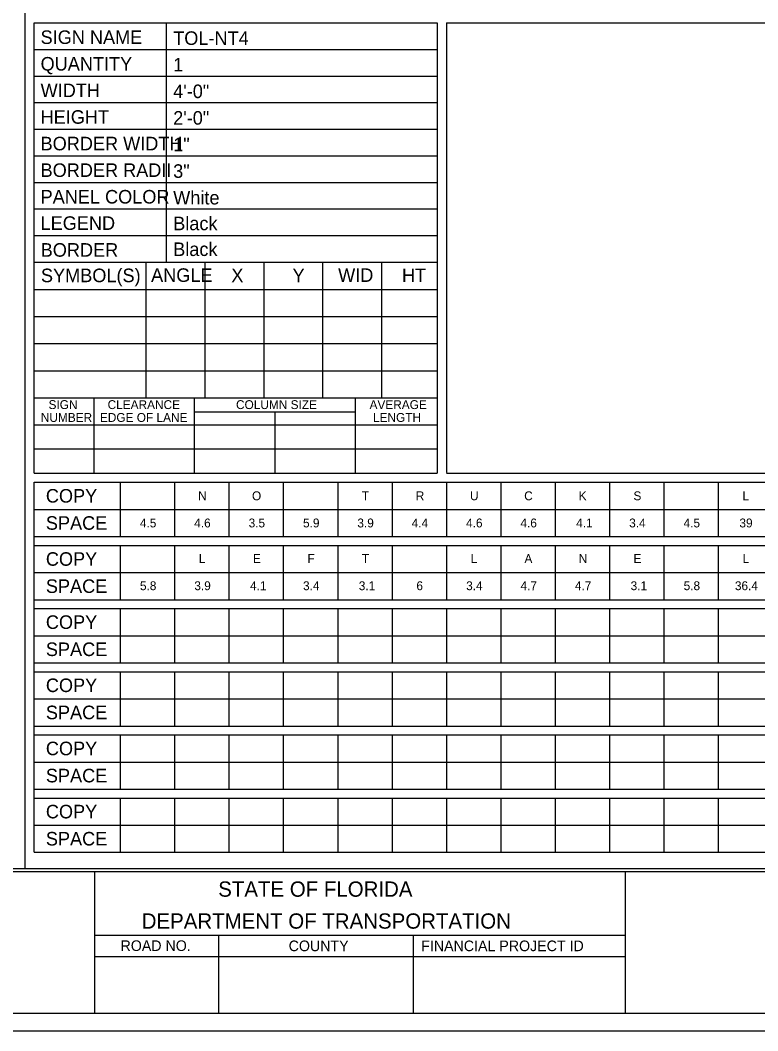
# Model space of a CAD drawing. Extents: x 17890628 to 17890844, y 17897506 to 17897992.
# Drawn here: x 17890772.14 to 17890808.43, y 17897507.81 to 17897557.55 of the extents above; entities that cross this region are included whole.
import ezdxf

# ---------------------------------------------------------------- set-up
doc = ezdxf.new("R2010")
doc.units = 0
for name, color, linetype in [('GSSign', 7, 'Continuous'), ('PlotBorder_dp', 7, 'Continuous'), ('SheetBorder_dp', 7, 'Continuous'), ('SheetLines_dp', 7, 'Continuous'), ('SheetLinesMisc2_dp', 7, 'Continuous'), ('TextMinor', 7, 'Continuous'), ('TextMisc', 7, 'Continuous')]:
    doc.layers.add(name, color=color, linetype=linetype)

msp = doc.modelspace()

# ---------------------------------------------------------------- linework, layer by layer
at = {"layer": 'PlotBorder_dp'}
msp.add_lwpolyline([(17890700.471, 17897507.81), (17890844.155, 17897507.81), (17890844.155, 17897600.116), (17890700.471, 17897600.116)], close=True, dxfattribs=at)
at = {"layer": 'SheetBorder_dp'}
for p, q in [((17890705.26, 17897515.647), (17890839.365, 17897515.647)), ((17890705.26, 17897508.681), (17890839.365, 17897508.681))]:
    msp.add_line(p, q, dxfattribs=at)
at = {"layer": 'SheetLines_dp'}
for p, q in [((17890775.796, 17897515.647), (17890775.796, 17897508.681)), ((17890801.92, 17897508.681), (17890801.92, 17897515.647)), ((17890775.796, 17897512.512), (17890801.92, 17897512.512)), ((17890781.892, 17897512.512), (17890781.892, 17897508.681)), ((17890791.471, 17897512.512), (17890791.471, 17897508.681)), ((17890775.796, 17897511.467), (17890801.92, 17897511.467))]:
    msp.add_line(p, q, dxfattribs=at)
at = {"layer": 'SheetLinesMisc2_dp'}
for p, q in [((17890772.367, 17897599.039), (17890772.367, 17897515.791)), ((17890772.823, 17897535.261), (17890772.823, 17897557.416)), ((17890772.823, 17897557.416), (17890792.654, 17897557.416)), ((17890779.324, 17897557.416), (17890779.324, 17897545.635)), ((17890792.654, 17897557.416), (17890792.654, 17897535.261)), ((17890793.11, 17897557.416), (17890793.11, 17897535.291)), ((17890793.11, 17897557.415), (17890838.594, 17897557.415)), ((17890772.823, 17897556.108), (17890792.654, 17897556.108)), ((17890772.823, 17897554.799), (17890792.654, 17897554.799)), ((17890772.823, 17897553.49), (17890792.654, 17897553.49)), ((17890772.823, 17897552.182), (17890792.654, 17897552.182)), ((17890772.823, 17897550.873), (17890792.654, 17897550.873)), ((17890772.823, 17897549.564), (17890792.654, 17897549.564)), ((17890772.823, 17897548.256), (17890782.738, 17897548.256)), ((17890782.738, 17897548.256), (17890792.654, 17897548.256)), ((17890772.823, 17897546.947), (17890782.738, 17897546.947)), ((17890782.738, 17897546.947), (17890792.654, 17897546.947)), ((17890772.823, 17897545.635), (17890792.654, 17897545.635)), ((17890778.326, 17897545.635), (17890778.326, 17897538.954)), ((17890781.223, 17897545.635), (17890781.223, 17897538.954)), ((17890784.121, 17897545.635), (17890784.121, 17897538.954)), ((17890787.018, 17897545.635), (17890787.018, 17897538.954)), ((17890789.916, 17897545.635), (17890789.916, 17897538.954)), ((17890772.823, 17897544.299), (17890792.654, 17897544.299)), ((17890772.823, 17897542.963), (17890792.654, 17897542.963)), ((17890772.823, 17897541.627), (17890792.654, 17897541.627)), ((17890772.823, 17897540.29), (17890792.654, 17897540.29)), ((17890772.823, 17897538.954), (17890792.654, 17897538.954)), ((17890775.761, 17897538.954), (17890775.761, 17897535.261)), ((17890780.696, 17897538.954), (17890780.696, 17897535.261)), ((17890788.628, 17897538.954), (17890788.628, 17897535.261)), ((17890780.696, 17897538.274), (17890788.628, 17897538.274)), ((17890784.663, 17897538.274), (17890784.663, 17897535.261)), ((17890772.823, 17897537.635), (17890792.654, 17897537.635)), ((17890772.823, 17897536.448), (17890792.654, 17897536.448)), ((17890772.823, 17897535.261), (17890792.654, 17897535.261)), ((17890793.11, 17897535.26), (17890838.594, 17897535.26)), ((17890772.824, 17897534.804), (17890838.594, 17897534.804)), ((17890772.824, 17897516.593), (17890772.824, 17897534.804)), ((17890777.058, 17897534.804), (17890777.058, 17897532.131)), ((17890779.733, 17897534.804), (17890779.733, 17897532.131)), ((17890782.408, 17897534.804), (17890782.408, 17897532.131)), ((17890785.084, 17897534.804), (17890785.084, 17897532.131)), ((17890787.76, 17897534.804), (17890787.76, 17897532.131)), ((17890790.435, 17897534.804), (17890790.435, 17897532.131)), ((17890793.11, 17897534.804), (17890793.11, 17897532.131)), ((17890795.786, 17897534.804), (17890795.786, 17897532.131)), ((17890798.462, 17897534.804), (17890798.462, 17897532.131)), ((17890801.137, 17897534.804), (17890801.137, 17897532.131)), ((17890803.813, 17897534.804), (17890803.813, 17897532.131)), ((17890806.488, 17897534.804), (17890806.488, 17897532.131)), ((17890772.824, 17897533.468), (17890838.594, 17897533.468)), ((17890772.824, 17897532.131), (17890838.594, 17897532.131)), ((17890772.824, 17897531.696), (17890838.594, 17897531.696)), ((17890777.058, 17897531.696), (17890777.058, 17897529.023)), ((17890779.733, 17897531.696), (17890779.733, 17897529.023)), ((17890782.408, 17897531.696), (17890782.408, 17897529.023)), ((17890785.084, 17897531.696), (17890785.084, 17897529.023)), ((17890787.76, 17897531.696), (17890787.76, 17897529.023)), ((17890790.435, 17897531.696), (17890790.435, 17897529.023)), ((17890793.11, 17897531.696), (17890793.11, 17897529.023)), ((17890795.786, 17897531.696), (17890795.786, 17897529.023)), ((17890798.462, 17897531.696), (17890798.462, 17897529.023)), ((17890801.137, 17897531.696), (17890801.137, 17897529.023)), ((17890803.813, 17897531.696), (17890803.813, 17897529.023)), ((17890806.488, 17897531.696), (17890806.488, 17897529.023)), ((17890772.824, 17897530.359), (17890838.594, 17897530.359)), ((17890772.824, 17897529.023), (17890838.594, 17897529.023)), ((17890772.824, 17897528.588), (17890838.594, 17897528.588)), ((17890777.058, 17897528.588), (17890777.058, 17897525.916)), ((17890779.733, 17897528.588), (17890779.733, 17897525.916)), ((17890782.408, 17897528.588), (17890782.408, 17897525.916)), ((17890785.084, 17897528.588), (17890785.084, 17897525.916)), ((17890787.76, 17897528.588), (17890787.76, 17897525.916)), ((17890790.435, 17897528.588), (17890790.435, 17897525.916)), ((17890793.11, 17897528.588), (17890793.11, 17897525.916)), ((17890795.786, 17897528.588), (17890795.786, 17897525.916)), ((17890798.462, 17897528.588), (17890798.462, 17897525.916)), ((17890801.137, 17897528.588), (17890801.137, 17897525.916)), ((17890803.813, 17897528.588), (17890803.813, 17897525.916)), ((17890806.488, 17897528.588), (17890806.488, 17897525.916)), ((17890772.824, 17897527.252), (17890838.594, 17897527.252)), ((17890772.824, 17897525.916), (17890838.594, 17897525.916)), ((17890772.824, 17897525.48), (17890838.594, 17897525.48)), ((17890777.058, 17897525.48), (17890777.058, 17897522.808)), ((17890779.733, 17897525.48), (17890779.733, 17897522.808)), ((17890782.408, 17897525.48), (17890782.408, 17897522.808)), ((17890785.084, 17897525.48), (17890785.084, 17897522.808)), ((17890787.76, 17897525.48), (17890787.76, 17897522.808)), ((17890790.435, 17897525.48), (17890790.435, 17897522.808)), ((17890793.11, 17897525.48), (17890793.11, 17897522.808)), ((17890795.786, 17897525.48), (17890795.786, 17897522.808)), ((17890798.462, 17897525.48), (17890798.462, 17897522.808)), ((17890801.137, 17897525.48), (17890801.137, 17897522.808)), ((17890803.813, 17897525.48), (17890803.813, 17897522.808)), ((17890806.488, 17897525.48), (17890806.488, 17897522.808)), ((17890772.824, 17897524.145), (17890838.594, 17897524.145)), ((17890772.824, 17897522.808), (17890838.594, 17897522.808)), ((17890772.824, 17897522.372), (17890838.594, 17897522.372)), ((17890777.058, 17897522.372), (17890777.058, 17897519.7)), ((17890779.733, 17897522.372), (17890779.733, 17897519.7)), ((17890782.408, 17897522.372), (17890782.408, 17897519.7)), ((17890785.084, 17897522.372), (17890785.084, 17897519.7)), ((17890787.76, 17897522.372), (17890787.76, 17897519.7)), ((17890790.435, 17897522.372), (17890790.435, 17897519.7)), ((17890793.11, 17897522.372), (17890793.11, 17897519.7)), ((17890795.786, 17897522.372), (17890795.786, 17897519.7)), ((17890798.462, 17897522.372), (17890798.462, 17897519.7)), ((17890801.137, 17897522.372), (17890801.137, 17897519.7)), ((17890803.813, 17897522.372), (17890803.813, 17897519.7)), ((17890806.488, 17897522.372), (17890806.488, 17897519.7)), ((17890772.824, 17897521.036), (17890838.594, 17897521.036)), ((17890772.824, 17897519.7), (17890838.594, 17897519.7)), ((17890772.824, 17897519.264), (17890838.594, 17897519.264)), ((17890777.058, 17897519.264), (17890777.058, 17897516.593)), ((17890779.733, 17897519.264), (17890779.733, 17897516.593)), ((17890782.408, 17897519.264), (17890782.408, 17897516.593)), ((17890785.084, 17897519.264), (17890785.084, 17897516.593)), ((17890787.76, 17897519.264), (17890787.76, 17897516.593)), ((17890790.435, 17897519.264), (17890790.435, 17897516.593)), ((17890793.11, 17897519.264), (17890793.11, 17897516.593)), ((17890795.786, 17897519.264), (17890795.786, 17897516.593)), ((17890798.462, 17897519.264), (17890798.462, 17897516.593)), ((17890801.137, 17897519.264), (17890801.137, 17897516.593)), ((17890803.813, 17897519.264), (17890803.813, 17897516.593)), ((17890806.488, 17897519.264), (17890806.488, 17897516.593)), ((17890772.824, 17897517.928), (17890838.594, 17897517.928)), ((17890772.824, 17897516.593), (17890838.594, 17897516.593)), ((17890705.5, 17897515.791), (17890839.233, 17897515.791))]:
    msp.add_line(p, q, dxfattribs=at)

# ---------------------------------------------------------------- texts
at = {"layer": 'GSSign'}
for s, height, p in [('TOL-NT4', 0.6667, (17890779.667, 17897556.331)), ('1', 0.667, (17890779.667, 17897555.022)), ('4\'-0"', 0.6667, (17890779.667, 17897553.713)), ('2\'-0"', 0.6667, (17890779.667, 17897552.405)), ('1"', 0.6667, (17890779.667, 17897551.096)), ('3"', 0.6667, (17890779.667, 17897549.788)), ('White', 0.6667, (17890779.667, 17897548.479)), ('Black', 0.6667, (17890779.667, 17897547.21)), ('Black', 0.6667, (17890779.667, 17897545.941)), ('N', 0.436, (17890780.894, 17897533.921)), ('O', 0.436, (17890783.545, 17897533.921)), ('T', 0.436, (17890788.948, 17897533.921)), ('R', 0.436, (17890791.602, 17897533.921)), ('U', 0.436, (17890794.271, 17897533.921)), ('C', 0.436, (17890796.938, 17897533.921)), ('K', 0.436, (17890799.618, 17897533.921)), ('S', 0.436, (17890802.314, 17897533.921)), ('L', 0.436, (17890807.678, 17897533.921)), ('4.5', 0.4357, (17890778.029, 17897532.584)), ('4.6', 0.4357, (17890780.701, 17897532.584)), ('3.5', 0.4357, (17890783.379, 17897532.584)), ('5.9', 0.4357, (17890786.055, 17897532.584)), ('3.9', 0.4357, (17890788.729, 17897532.584)), ('4.4', 0.4357, (17890791.403, 17897532.584)), ('4.6', 0.4357, (17890794.078, 17897532.584)), ('4.6', 0.4357, (17890796.753, 17897532.584)), ('4.1', 0.4357, (17890799.496, 17897532.584)), ('3.4', 0.4357, (17890802.104, 17897532.584)), ('4.5', 0.4357, (17890804.781, 17897532.584)), ('39', 0.4357, (17890807.528, 17897532.584)), ('L', 0.436, (17890780.929, 17897530.831)), ('E', 0.436, (17890783.59, 17897530.831)), ('F', 0.436, (17890786.274, 17897530.831)), ('T', 0.436, (17890788.952, 17897530.831)), ('L', 0.436, (17890794.305, 17897530.831)), ('A', 0.436, (17890796.951, 17897530.831)), ('N', 0.436, (17890799.625, 17897530.831)), ('E', 0.436, (17890802.317, 17897530.831)), ('L', 0.436, (17890807.682, 17897530.831)), ('5.8', 0.4357, (17890778.031, 17897529.495)), ('3.9', 0.4357, (17890780.707, 17897529.495)), ('4.1', 0.4357, (17890783.448, 17897529.495)), ('3.4', 0.4357, (17890786.056, 17897529.495)), ('3.1', 0.4357, (17890788.799, 17897529.495)), ('6', 0.436, (17890791.634, 17897529.495)), ('3.4', 0.4357, (17890794.082, 17897529.495)), ('4.7', 0.4357, (17890796.757, 17897529.495)), ('4.7', 0.4357, (17890799.433, 17897529.495)), ('3.1', 0.4357, (17890802.175, 17897529.495)), ('5.8', 0.4357, (17890804.784, 17897529.495)), ('36.4', 0.4357, (17890807.306, 17897529.495))]:
    msp.add_text(s, height=height, dxfattribs=at).set_placement(p)
at = {"layer": 'TextMinor'}
for s, height, p in [('SIGN NAME', 0.6667, (17890773.142, 17897556.376)), ('QUANTITY', 0.6667, (17890773.142, 17897555.068)), ('WIDTH', 0.6667, (17890773.142, 17897553.759)), ('HEIGHT', 0.6667, (17890773.142, 17897552.45)), ('BORDER WIDTH', 0.66667, (17890773.142, 17897551.142)), ('BORDER RADII', 0.66667, (17890773.142, 17897549.833)), ('PANEL COLOR', 0.66667, (17890773.142, 17897548.524)), ('LEGEND', 0.6667, (17890773.142, 17897547.227)), ('BORDER', 0.6667, (17890773.148, 17897545.907)), ('SYMBOL(S)', 0.6667, (17890773.16, 17897544.653)), ('ANGLE', 0.6667, (17890778.58, 17897544.667)), ('X', 0.667, (17890782.527, 17897544.653)), ('Y', 0.667, (17890785.54, 17897544.653)), ('WID', 0.6667, (17890787.784, 17897544.667)), ('HT', 0.6667, (17890790.925, 17897544.654)), ('SIGN', 0.4357, (17890773.533, 17897538.41)), ('CLEARANCE', 0.4357, (17890776.44, 17897538.408)), ('COLUMN SIZE', 0.43573, (17890782.758, 17897538.408)), ('AVERAGE', 0.4357, (17890789.329, 17897538.408)), ('NUMBER', 0.4357, (17890773.154, 17897537.776)), ('EDGE OF LANE', 0.43573, (17890776.061, 17897537.776)), ('LENGTH', 0.4357, (17890789.498, 17897537.776)), ('COPY', 0.6667, (17890773.402, 17897533.805)), ('SPACE', 0.6667, (17890773.402, 17897532.468)), ('COPY', 0.6667, (17890773.402, 17897530.696)), ('SPACE', 0.6667, (17890773.402, 17897529.36)), ('COPY', 0.6667, (17890773.402, 17897527.589)), ('SPACE', 0.6667, (17890773.402, 17897526.253)), ('COPY', 0.6667, (17890773.402, 17897524.48)), ('SPACE', 0.6667, (17890773.402, 17897523.145)), ('COPY', 0.6667, (17890773.402, 17897521.372)), ('SPACE', 0.6667, (17890773.402, 17897520.036)), ('COPY', 0.6667, (17890773.402, 17897518.264)), ('SPACE', 0.6667, (17890773.402, 17897516.929))]:
    msp.add_text(s, height=height, dxfattribs=at).set_placement(p)
at = {"layer": 'TextMisc'}
for s, height, p in [('STATE OF FLORIDA', 0.75238, (17890781.882, 17897514.408)), ('DEPARTMENT OF TRANSPORTATION', 0.75238, (17890778.118, 17897512.836)), ('ROAD NO.', 0.5225, (17890777.076, 17897511.737)), ('COUNTY', 0.5225, (17890785.349, 17897511.728)), ('FINANCIAL PROJECT ID', 0.52249, (17890791.871, 17897511.728))]:
    msp.add_text(s, height=height, dxfattribs=at).set_placement(p)

doc.saveas('drawing.dxf')
